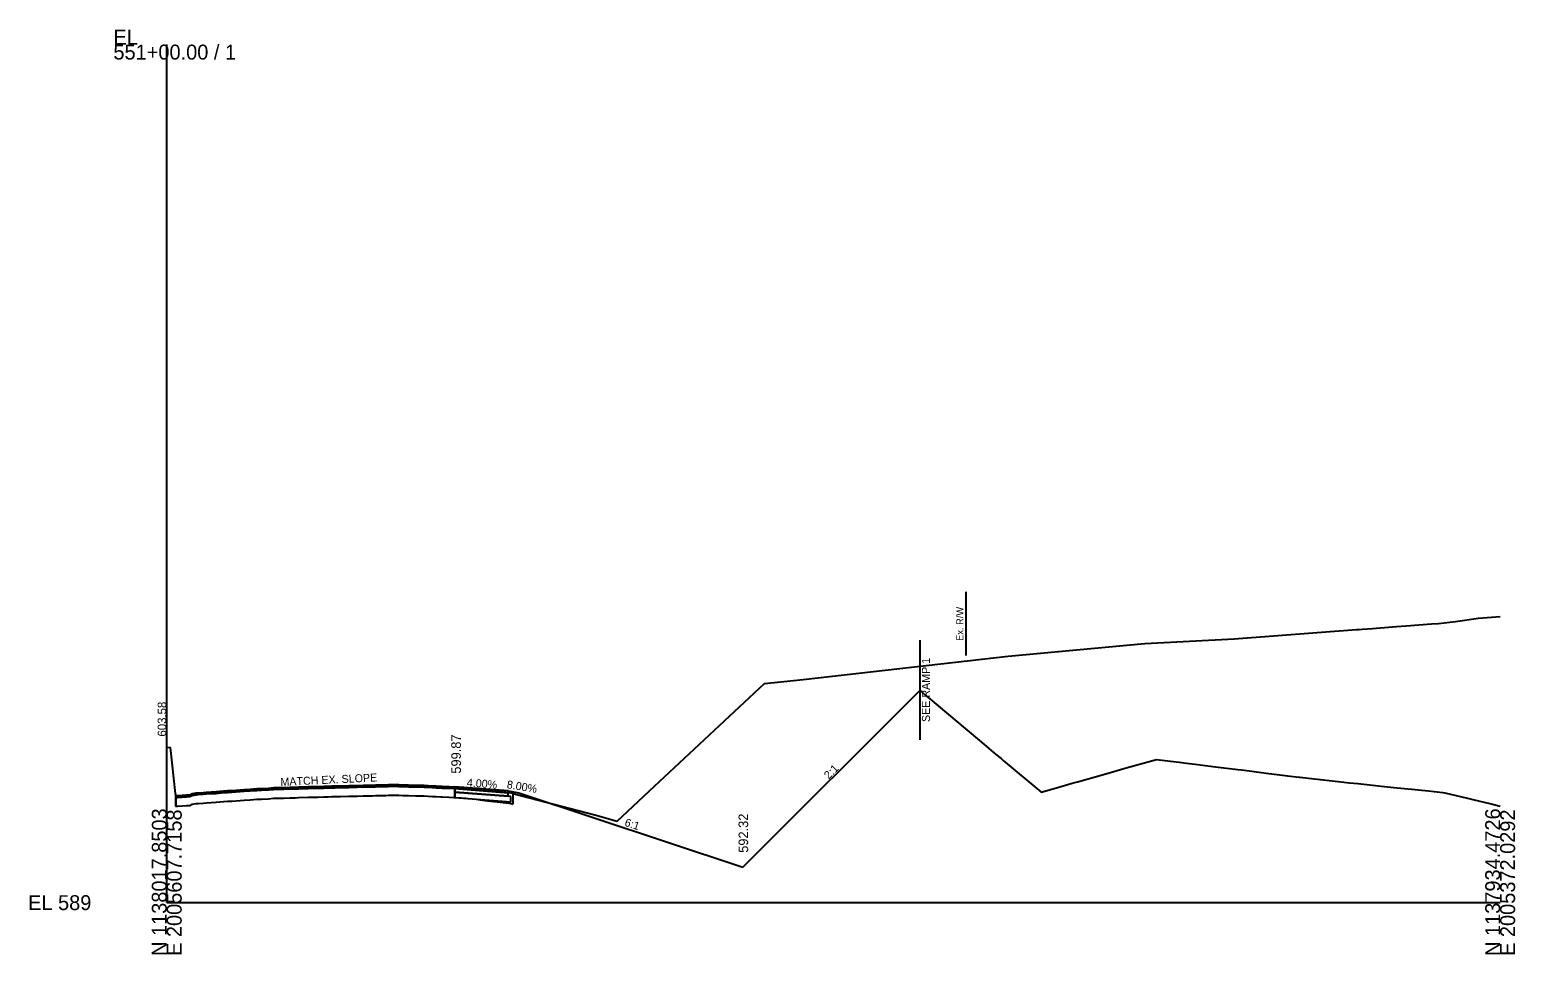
# Model space of a CAD drawing. Extents: x -201 to 2007062, y -213 to 1139737.
# Drawn here: x -25.7 to 252.8, y 6490.3 to 6663.8 of the extents above; entities that cross this region are included whole.
import ezdxf

# ---------------------------------------------------------------- set-up
doc = ezdxf.new("R2010")
doc.units = 0
for name, color, linetype in [('Default', 7, 'Continuous'), ('RD_DTM_Design_FG', 7, 'Continuous'), ('RD_GPK_XS_Cell', 7, 'Continuous'), ('RD_Sketch1', 7, 'Continuous'), ('RD_XS_Base', 7, 'Continuous'), ('RD_XS_EarthShd', 7, 'Continuous'), ('RD_XS_ExGround', 7, 'Continuous'), ('RD_XS_ExPaveRet', 7, 'Continuous'), ('RD_XS_ExRW', 7, 'Continuous'), ('RD_XS_PaveOvlay', 7, 'Continuous'), ('RD_XS_PaveShd', 7, 'Continuous'), ('RD_XS_SideStreet', 7, 'Continuous'), ('RD_XS_TieSlope', 7, 'Continuous'), ('RD_XS_TX_Ditch', 7, 'Continuous'), ('RD_XS_TX_Elev_EX', 7, 'Continuous'), ('RD_XS_TX_Elev_PR', 7, 'Continuous'), ('RD_XS_TX_Slope', 7, 'Continuous')]:
    doc.layers.add(name, color=color, linetype=linetype)

msp = doc.modelspace()

# ---------------------------------------------------------------- linework, layer by layer
at = {"layer": 'RD_DTM_Design_FG'}
msp.add_lwpolyline([(141.19, 6539.85), (141.7, 6539.41), (142.41, 6538.81), (143.07, 6538.26), (149.7, 6532.68), (152.76, 6530.11), (155.41, 6527.88), (156.42, 6527.04), (156.85, 6526.68), (163.87, 6520.81), (163.95, 6520.75), (166.8, 6521.56), (169.73, 6522.39), (170.77, 6522.69), (174.34, 6523.7), (177.54, 6524.61), (179.46, 6525.15), (184.19, 6526.49), (185.55, 6526.88), (190.35, 6526.27), (190.72, 6526.23), (191.71, 6526.1), (192.81, 6525.97), (194.69, 6525.73), (197.15, 6525.43), (197.67, 6525.36), (198.2, 6525.3), (200.35, 6525.03), (200.83, 6524.97), (201.51, 6524.89), (203.46, 6524.64), (206.13, 6524.29), (209.67, 6523.87), (210.11, 6523.82), (212.34, 6523.56), (212.5, 6523.54), (215.16, 6523.23), (215.78, 6523.16), (219.09, 6522.78), (221.78, 6522.5), (223.34, 6522.33), (227.17, 6521.94), (227.69, 6521.88), (230.71, 6521.57), (233.39, 6521.3), (233.5, 6521.29), (234.64, 6521.17), (236.57, 6520.96), (237.64, 6520.85), (239.23, 6520.68), (239.65, 6520.63), (243.85, 6519.6), (244.86, 6519.35), (248.33, 6518.51), (250, 6518.1)], dxfattribs=at)
at = {"layer": 'RD_GPK_XS_Cell'}
for q in [(0, 6660.99), (250, 6500)]:
    msp.add_line((0, 6500), q, dxfattribs=at)
at = {"layer": 'RD_XS_Base'}
for points in [[(64.02, 6520.62), (54.02, 6521.41)], [(54.02, 6521.41), (54.02, 6520.75)], [(64.52, 6519.92), (64.02, 6519.96), (54.02, 6520.75)], [(54.02, 6520.75), (54.02, 6519.75)], [(54.02, 6520.75), (64.02, 6519.96)], [(64.02, 6519.96), (64.02, 6520.62)], [(54.02, 6519.75), (64.52, 6518.92)], [(64.52, 6518.92), (64.52, 6519.92)]]:
    msp.add_lwpolyline(points, dxfattribs=at)
at = {"layer": 'RD_XS_EarthShd'}
msp.add_lwpolyline([(64.02, 6520.95), (66.02, 6520.63)], dxfattribs=at)
at = {"layer": 'RD_XS_ExGround'}
msp.add_lwpolyline([(0, 6529.16), (0.66, 6529.14), (1.6, 6520.46), (1.69, 6520.06), (2.01, 6520.09), (2.88, 6520.14), (3.73, 6520.21), (4.3, 6520.23), (4.78, 6520.45), (5.53, 6520.58), (5.93, 6520.6), (6.85, 6520.67), (7.42, 6520.72), (9.25, 6520.84), (10.63, 6520.98), (11.37, 6521.02), (12.2, 6521.06), (13.76, 6521.18), (14.54, 6521.24), (15.61, 6521.32), (16.9, 6521.4), (17.77, 6521.43), (19.06, 6521.51), (20.03, 6521.59), (20.54, 6521.6), (21.6, 6521.61), (21.97, 6521.63), (23.17, 6521.66), (24.1, 6521.68), (24.73, 6521.7), (26.54, 6521.77), (27.87, 6521.81), (28.34, 6521.82), (29.43, 6521.84), (30.27, 6521.87), (30.98, 6521.9), (31.57, 6521.9), (32.58, 6521.92), (34.14, 6521.97), (34.7, 6521.98), (35.7, 6522.01), (36.82, 6522.05), (37.27, 6522.06), (38.53, 6522.07), (39.17, 6522.08), (41.07, 6522.13), (41.59, 6522.14), (42.5, 6522.16), (42.94, 6522.17), (43.54, 6522.15), (44.29, 6522.13), (45.31, 6522.09), (46.67, 6522.07), (47.43, 6522.04), (48.24, 6522.02), (49.81, 6521.93), (50.52, 6521.89), (51.37, 6521.86), (51.67, 6521.84), (52.94, 6521.79), (53.8, 6521.76), (54.21, 6521.73), (55.23, 6521.67), (56.07, 6521.6), (56.52, 6521.56), (58.01, 6521.42), (58.78, 6521.32), (60.16, 6521.09), (60.78, 6521.03), (62.52, 6520.87), (64.2, 6520.64), (64.55, 6520.58), (64.88, 6520.49), (80.25, 6516.45), (84.45, 6515.31), (91.47, 6521.86), (112.06, 6541.1), (119.32, 6541.86), (157.75, 6546.23), (183.38, 6548.63), (200.12, 6549.51), (223.09, 6551.25), (223.56, 6551.28), (224.16, 6551.33), (226.08, 6551.47), (227.54, 6551.58), (230.55, 6551.8), (232.41, 6551.94), (237.15, 6552.29), (238.42, 6552.39), (241.62, 6552.76), (245.94, 6553.35), (250, 6553.66)], dxfattribs=at)
at = {"layer": 'RD_XS_ExPaveRet'}
for p, q in [((54.02, 6520.75), (54.02, 6521.41)), ((54.02, 6519.75), (54.02, 6520.75)), ((64.88, 6520.49), (64.88, 6518.49)), ((1.69, 6518.06), (1.69, 6520.06)), ((1.69, 6519.73), (1.69, 6518.06)), ((1.69, 6518.06), (2.01, 6518.09)), ((1.69, 6518.06), (2.01, 6518.09)), ((2.01, 6518.09), (2.88, 6518.14)), ((2.01, 6518.09), (2.88, 6518.14)), ((2.88, 6518.14), (3.73, 6518.21)), ((2.88, 6518.14), (3.73, 6518.21)), ((3.73, 6518.21), (4.3, 6518.23)), ((3.73, 6518.21), (4.3, 6518.23)), ((4.3, 6518.23), (4.78, 6518.45)), ((4.3, 6518.23), (4.78, 6518.45)), ((4.78, 6518.45), (5.53, 6518.58)), ((4.78, 6518.45), (5.53, 6518.58)), ((5.53, 6518.58), (5.93, 6518.6)), ((5.53, 6518.58), (5.93, 6518.6)), ((5.93, 6518.6), (6.85, 6518.67)), ((5.93, 6518.6), (6.85, 6518.67)), ((6.85, 6518.67), (7.42, 6518.72)), ((6.85, 6518.67), (7.42, 6518.72)), ((7.42, 6518.72), (9.25, 6518.84)), ((7.42, 6518.72), (9.25, 6518.84)), ((9.25, 6518.84), (10.63, 6518.98)), ((9.25, 6518.84), (10.63, 6518.98)), ((10.63, 6518.98), (11.37, 6519.02)), ((10.63, 6518.98), (11.37, 6519.02)), ((11.37, 6519.02), (12.2, 6519.06)), ((11.37, 6519.02), (12.2, 6519.06)), ((12.2, 6519.06), (13.76, 6519.18)), ((12.2, 6519.06), (13.76, 6519.18)), ((13.76, 6519.18), (14.54, 6519.24)), ((13.76, 6519.18), (14.54, 6519.24)), ((14.54, 6519.24), (15.61, 6519.32)), ((14.54, 6519.24), (15.61, 6519.32)), ((15.61, 6519.32), (16.9, 6519.4)), ((15.61, 6519.32), (16.9, 6519.4)), ((16.9, 6519.4), (17.77, 6519.43)), ((16.9, 6519.4), (17.77, 6519.43)), ((17.77, 6519.43), (19.06, 6519.51)), ((17.77, 6519.43), (19.06, 6519.51)), ((19.06, 6519.51), (20.03, 6519.59)), ((19.06, 6519.51), (20.03, 6519.59)), ((20.03, 6519.59), (20.54, 6519.6)), ((20.03, 6519.59), (20.54, 6519.6)), ((20.54, 6519.6), (21.6, 6519.61)), ((20.54, 6519.6), (21.6, 6519.61)), ((21.6, 6519.61), (21.97, 6519.63)), ((21.6, 6519.61), (21.97, 6519.63)), ((21.97, 6519.63), (23.17, 6519.66)), ((21.97, 6519.63), (23.17, 6519.66)), ((23.17, 6519.66), (24.1, 6519.68)), ((23.17, 6519.66), (24.1, 6519.68)), ((24.1, 6519.68), (24.73, 6519.7)), ((24.1, 6519.68), (24.73, 6519.7)), ((24.73, 6519.7), (26.54, 6519.77)), ((24.73, 6519.7), (26.54, 6519.77)), ((26.54, 6519.77), (27.87, 6519.81)), ((26.54, 6519.77), (27.87, 6519.81)), ((27.87, 6519.81), (28.34, 6519.82)), ((27.87, 6519.81), (28.34, 6519.82)), ((28.34, 6519.82), (29.43, 6519.84)), ((28.34, 6519.82), (29.43, 6519.84)), ((29.43, 6519.84), (30.27, 6519.87)), ((29.43, 6519.84), (30.27, 6519.87)), ((30.27, 6519.87), (30.98, 6519.9)), ((30.27, 6519.87), (30.98, 6519.9)), ((30.98, 6519.9), (31.57, 6519.9)), ((30.98, 6519.9), (31.57, 6519.9)), ((31.57, 6519.9), (32.58, 6519.92)), ((31.57, 6519.9), (32.58, 6519.92)), ((32.58, 6519.92), (34.14, 6519.97)), ((32.58, 6519.92), (34.14, 6519.97)), ((34.14, 6519.97), (34.7, 6519.98)), ((34.14, 6519.97), (34.7, 6519.98)), ((34.7, 6519.98), (35.7, 6520.01)), ((34.7, 6519.98), (35.7, 6520.01)), ((35.7, 6520.01), (36.82, 6520.05)), ((35.7, 6520.01), (36.82, 6520.05)), ((36.82, 6520.05), (37.27, 6520.06)), ((36.82, 6520.05), (37.27, 6520.06)), ((37.27, 6520.06), (38.53, 6520.07)), ((37.27, 6520.06), (38.53, 6520.07)), ((38.53, 6520.07), (39.17, 6520.08)), ((38.53, 6520.07), (39.17, 6520.08)), ((39.17, 6520.08), (41.07, 6520.13)), ((39.17, 6520.08), (41.07, 6520.13)), ((41.07, 6520.13), (41.59, 6520.14)), ((41.07, 6520.13), (41.59, 6520.14)), ((41.59, 6520.14), (42.5, 6520.16)), ((41.59, 6520.14), (42.5, 6520.16)), ((42.5, 6520.16), (42.94, 6520.17)), ((42.5, 6520.16), (42.94, 6520.17)), ((42.94, 6520.17), (43.54, 6520.15)), ((42.94, 6520.17), (43.54, 6520.15)), ((43.54, 6520.15), (44.29, 6520.13)), ((43.54, 6520.15), (44.29, 6520.13)), ((44.29, 6520.13), (45.31, 6520.09)), ((44.29, 6520.13), (45.31, 6520.09)), ((45.31, 6520.09), (46.67, 6520.07)), ((45.31, 6520.09), (46.67, 6520.07)), ((46.67, 6520.07), (47.43, 6520.04)), ((46.67, 6520.07), (47.43, 6520.04)), ((47.43, 6520.04), (48.24, 6520.02)), ((47.43, 6520.04), (48.24, 6520.02)), ((48.24, 6520.02), (49.81, 6519.93)), ((48.24, 6520.02), (49.81, 6519.93)), ((49.81, 6519.93), (50.52, 6519.89)), ((49.81, 6519.93), (50.52, 6519.89)), ((50.52, 6519.89), (51.37, 6519.86)), ((50.52, 6519.89), (51.37, 6519.86)), ((51.37, 6519.86), (51.67, 6519.84)), ((51.37, 6519.86), (51.67, 6519.84)), ((51.67, 6519.84), (52.94, 6519.79)), ((51.67, 6519.84), (52.94, 6519.79)), ((52.94, 6519.79), (53.8, 6519.76)), ((52.94, 6519.79), (53.8, 6519.76)), ((53.8, 6519.76), (54.21, 6519.73)), ((53.8, 6519.76), (54.02, 6519.74)), ((54.02, 6519.75), (54.02, 6519.74)), ((54.02, 6519.74), (54.02, 6519.75)), ((54.21, 6519.73), (55.23, 6519.67)), ((55.23, 6519.67), (56.07, 6519.6)), ((56.07, 6519.6), (56.52, 6519.56)), ((56.52, 6519.56), (58.01, 6519.42)), ((58.01, 6519.42), (58.78, 6519.32)), ((58.78, 6519.32), (60.16, 6519.09)), ((60.16, 6519.09), (60.78, 6519.03)), ((60.78, 6519.03), (62.52, 6518.87)), ((62.52, 6518.87), (64.2, 6518.64)), ((64.2, 6518.64), (64.55, 6518.58)), ((64.55, 6518.58), (64.88, 6518.49))]:
    msp.add_line(p, q, dxfattribs=at)
for points in [[(54.02, 6521.41), (53.8, 6521.42), (52.94, 6521.46), (51.67, 6521.51), (51.37, 6521.52), (50.52, 6521.56), (49.81, 6521.59), (48.24, 6521.68), (47.43, 6521.71), (46.67, 6521.73), (45.31, 6521.76), (44.29, 6521.8), (43.54, 6521.82), (42.94, 6521.84), (42.5, 6521.83), (41.59, 6521.81), (41.07, 6521.8), (39.17, 6521.75), (38.53, 6521.74), (37.27, 6521.73), (36.82, 6521.72), (35.7, 6521.67), (34.7, 6521.65), (34.14, 6521.63), (32.58, 6521.59), (31.57, 6521.57), (30.98, 6521.57), (30.27, 6521.54), (29.43, 6521.51), (28.34, 6521.49), (27.87, 6521.48), (26.54, 6521.44), (24.73, 6521.37), (24.1, 6521.35), (23.17, 6521.33), (21.97, 6521.29), (21.6, 6521.28), (20.54, 6521.27), (20.03, 6521.25), (19.06, 6521.18), (17.77, 6521.1), (16.9, 6521.07), (15.61, 6520.99), (14.54, 6520.91), (13.76, 6520.85), (12.2, 6520.73), (11.37, 6520.69), (10.63, 6520.64), (9.25, 6520.51), (7.42, 6520.39), (6.85, 6520.33), (5.93, 6520.27), (5.53, 6520.25), (4.78, 6520.11), (4.3, 6519.89), (3.73, 6519.88), (2.88, 6519.81), (2.01, 6519.75), (1.69, 6519.73)], [(1.69, 6519.73), (1.69, 6519.73)]]:
    msp.add_lwpolyline(points, dxfattribs=at)
at = {"layer": 'RD_XS_ExRW'}
msp.add_line((149.85, 6558.35), (149.85, 6546.35), dxfattribs=at)
at = {"layer": 'RD_XS_PaveOvlay'}
for points in [[(1.69, 6520.06), (2.01, 6520.09), (2.88, 6520.14), (3.73, 6520.21), (4.3, 6520.23), (4.78, 6520.45), (5.53, 6520.58), (5.93, 6520.6), (6.85, 6520.67), (7.42, 6520.72), (9.25, 6520.84), (10.63, 6520.98), (11.37, 6521.02), (12.2, 6521.06), (13.76, 6521.18), (14.54, 6521.24), (15.61, 6521.32), (16.9, 6521.4), (17.77, 6521.43), (19.06, 6521.51), (20.03, 6521.59), (20.54, 6521.6), (21.6, 6521.61), (21.97, 6521.63), (23.17, 6521.66), (24.1, 6521.68), (24.73, 6521.7), (26.54, 6521.77), (27.87, 6521.81), (28.34, 6521.82), (29.43, 6521.84), (30.27, 6521.87), (30.98, 6521.9), (31.57, 6521.9), (32.58, 6521.92), (34.14, 6521.97), (34.7, 6521.98), (35.7, 6522.01), (36.82, 6522.05), (37.27, 6522.06), (38.53, 6522.07), (39.17, 6522.08), (41.07, 6522.13), (41.59, 6522.14), (42.5, 6522.16), (42.94, 6522.17), (43.54, 6522.15), (44.29, 6522.13), (45.31, 6522.09), (46.67, 6522.07), (47.43, 6522.04), (48.24, 6522.02), (49.81, 6521.93), (50.52, 6521.89), (51.37, 6521.86), (51.67, 6521.84), (52.94, 6521.79), (53.8, 6521.76), (54.02, 6521.74)], [(1.69, 6519.73), (2.01, 6519.75), (2.88, 6519.81), (3.73, 6519.88), (4.3, 6519.89), (4.78, 6520.11), (5.53, 6520.25), (5.93, 6520.27), (6.85, 6520.33), (7.42, 6520.39), (9.25, 6520.51), (10.63, 6520.64), (11.37, 6520.69), (12.2, 6520.73), (13.76, 6520.85), (14.54, 6520.91), (15.61, 6520.99), (16.9, 6521.07), (17.77, 6521.1), (19.06, 6521.18), (20.03, 6521.25), (20.54, 6521.27), (21.6, 6521.28), (21.97, 6521.29), (23.17, 6521.33), (24.1, 6521.35), (24.73, 6521.37), (26.54, 6521.44), (27.87, 6521.48), (28.34, 6521.49), (29.43, 6521.51), (30.27, 6521.54), (30.98, 6521.57), (31.57, 6521.57), (32.58, 6521.59), (34.14, 6521.63), (34.7, 6521.65), (35.7, 6521.67), (36.82, 6521.72), (37.27, 6521.73), (38.53, 6521.74), (39.17, 6521.75), (41.07, 6521.8), (41.59, 6521.81), (42.5, 6521.83), (42.94, 6521.84), (43.54, 6521.82), (44.29, 6521.8), (45.31, 6521.76), (46.67, 6521.73), (47.43, 6521.71), (48.24, 6521.68), (49.81, 6521.59), (50.52, 6521.56), (51.37, 6521.52), (51.67, 6521.51), (52.94, 6521.46), (53.8, 6521.42), (54.02, 6521.41)]]:
    msp.add_lwpolyline(points, dxfattribs=at)
at = {"layer": 'RD_XS_PaveShd'}
for points in [[(64.02, 6520.95), (54.02, 6521.75)], [(54.02, 6521.75), (54.02, 6521.41)], [(54.02, 6521.41), (64.02, 6520.62)], [(64.02, 6520.62), (64.02, 6520.95)]]:
    msp.add_lwpolyline(points, dxfattribs=at)
at = {"layer": 'RD_XS_SideStreet'}
msp.add_line((141.22, 6549.23), (141.22, 6530.55), dxfattribs=at)
at = {"layer": 'RD_XS_TieSlope'}
msp.add_line((66.02, 6520.63), (108.02, 6506.63), dxfattribs=at)
msp.add_lwpolyline([(108.02, 6506.63), (141.22, 6539.82)], dxfattribs=at)

# ---------------------------------------------------------------- texts
at = {"layer": 'Default'}
msp.add_text('-', height=0.0001, dxfattribs=at).set_placement((0, 6500))
at = {"layer": 'RD_GPK_XS_Cell'}
for s, p in [('EL', (-10, 6660.99)), ('551+00.00 / 1', (-10, 6658.19)), ('EL 589', (-26, 6498.6))]:
    msp.add_text(s, height=2.8, dxfattribs=at).set_placement(p)
for s, p in [('N 1138017.8503', (0, 6490)), ('E 2005607.7158', (2.8, 6490)), ('N 1137934.4726', (250, 6490)), ('E 2005372.0292', (252.8, 6490))]:
    msp.add_text(s, height=2.8, rotation=90, dxfattribs=at).set_placement(p)
at = {"layer": 'RD_Sketch1'}
for s, p in [('Exterior Boundary', (145.7, 6544.88)), ('LOC_C', (146.03, 6544.88)), ('Exterior Boundary', (53.46, 6521.7)), ('EP_X_R', (53.75, 6521.7)), ('EP_X2', (53.81, 6520.7)), ('EP_X1', (53.81, 6521.36)), ('551+00.00', (59.68, 6521.22)), ('ESP1_R', (63.75, 6520.57)), ('ESP_R', (63.79, 6520.9)), ('ES_R', (65.84, 6520.58)), ('EP_X3', (53.81, 6519.7)), ('ESP2_R', (63.75, 6519.91)), ('ESP4_R', (64.25, 6519.87)), ('ESP3_R', (64.25, 6518.87))]:
    msp.add_text(s, height=0.05, dxfattribs=at).set_placement(p)
at = {"layer": 'RD_XS_ExRW'}
msp.add_text('Ex. R/W ', height=1.3, rotation=90, dxfattribs=at).set_placement((149.35, 6549.12))
at = {"layer": 'RD_XS_SideStreet'}
msp.add_text('SEE RAMP 1', height=1.5, rotation=90, dxfattribs=at).set_placement((143.09, 6533.89))
at = {"layer": 'RD_XS_TX_Ditch'}
msp.add_text('592.32', height=1.8, rotation=90, dxfattribs=at).set_placement((109.01, 6509.35))
at = {"layer": 'RD_XS_TX_Elev_EX'}
msp.add_text('603.58', height=1.6, rotation=90, dxfattribs=at).set_placement((-0.1, 6531.16))
at = {"layer": 'RD_XS_TX_Elev_PR'}
msp.add_text('599.87', height=1.8, rotation=90, dxfattribs=at).set_placement((55.15, 6524.2))
at = {"layer": 'RD_XS_TX_Slope'}
for s, rotation, p in [('MATCH EX. SLOPE', 2.7318, (21.35, 6521.89)), ('4.00%', 355.4406, (56.22, 6521.82)), ('2:1', 44.9946, (124.12, 6523.08)), ('8.00%', 350.9242, (63.68, 6521.48)), ('6:1', 341.5788, (85.72, 6514.45))]:
    msp.add_text(s, height=1.5, rotation=rotation, dxfattribs=at).set_placement(p)

doc.saveas('drawing.dxf')
